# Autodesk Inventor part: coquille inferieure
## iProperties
Shininess: 20.0
Angle Display Precision: 2
Document Length Units: 11269
Document Angle Units: 11279
Document Time Units: 11290
Document Mass Units: 11283
Document Length Units Precision: 3
Document Angle Units Precision: 2
Compacted: True
Created: 2002-04
Part Number: coquille inferieure
Material: Par défaut
Document SubType Name: Modélisation
Designer: thchene
Density: 0.0
Volumn: 0.0
Area: 0.0
PropertySet Name: Model Information
Control State: 0
Master: False
Checked Out: False
Author: thchene
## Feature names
1. Extrusion1
2. Lissage1
3. Révolution1 [Revolution]
4. Révolution2 [Revolution]
5. Révolution3 [Revolution]
6. Révolution4 [Revolution]
7. Symétrie2 [Mirror]
8. Extrusion14
9. Extrusion15
10. Congé1 [Fillet]
11. Lissage3
12. Extrusion6
13. Extrusion7
14. Extrusion8
15. Extrusion9
16. Extrusion10
17. Extrusion11
18. Perçage2 [Hole]
19. Symétrie3 [Mirror]
20. Extrusion16
21. Congé5 [Fillet]
22. Congé6 [Fillet]
23. Congé7 [Fillet]
24. Extrusion13
